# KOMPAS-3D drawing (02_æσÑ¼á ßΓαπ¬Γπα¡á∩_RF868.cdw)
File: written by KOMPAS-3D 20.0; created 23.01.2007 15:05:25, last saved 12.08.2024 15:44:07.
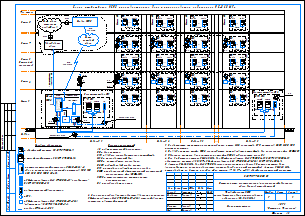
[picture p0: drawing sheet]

Sheet 1: A3, landscape

Document properties: Разработал: Антошин; Проверил: Тарасов; Утвердил: Шмончев; Н. контр.: Силаков; Количество листов документа: 1; Полное имя файла: \\s-tech\depts\Отдел_ПКО\Проекты\Типовые проекты МКД 2023\!Типовой проект\2_Типовой проект МКД_Радиоканал\02_Схема структурная_RF868.cdw; Материал: Многоквартирный жилой дом с использованием УСПД

Title block, sheet 1: Наименование: ВЛСТ 858.00.001 С3; designation: ВЛСТ 1177.02.000 С3; Количество листов документа: 8; organisation: АО ГК / "Системы и Технологии"; Форматы листов документа: A3; stored path: Y:\Проекты\ЭнергоКурган\Типовой проект\02_Рабочая док. общ\Е1_001_Сх деления.cdw; cell 302: Система учета электроэнергии (с организацией удаленного / сбора данных) потребителей; cell 303: Типовой проект ИСУЭ / многоквартирного дома с использованием / радиоканала (F2/868 МГц); cell 304: Схема структурная АИИС; cell 320: Р

Referenced files in \\Helios\отдел_пко\Общая папка Компас\_Addons\Signatures\: Signatures.lfr|Тарасов, Signatures.lfr, Signatures.lfr|Силаков, Signatures.lfr|Шмончев
Referenced files in C:\Program Files\ASCON\KOMPAS-3D V13\Libs\_Addons\Signatures\: Signatures.lfr
Referenced files: qlkzkl.frw, eiczbt.frw, hsklda.frw
Referenced files in C:\Program Files\ASCON\KOMPAS-3D v20\Sys\: Lighting.lts
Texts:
  Тарасов
  Силаков
  Шмончев
  Лит-Масса-Масштаб
  Материал-Предприятие
  Normal
  TXT
  Plain Text
  Centerline
  Outline
  Этаж 1
  ВВГнг(А)-LS 3х2.5
  Схема структурная ИСУЭ многоквартирного дома с использованием радиоканала RF-868 МГц
  Тех. этаж
  Шкаф
  УСПД
  ПЭФ
  RS-485
  SM160-02
  USB
  Link ST200
  Антенна GSM
  Электрощитовая №1
  ВРУ №1
  Сч. ОДПУ
  Сч. МОП
  ПРК
  ВРУ №2
  Электрощитовая №2
  RF-868
  Сч. Кв.1
  Сч. Кв.6
  ВОЛС
  Оборудование
  связи
  Этаж N
  GSM
  Осн. канал
  Сервер ИСУЭ
  Стояк ЭЭ
  Этаж 7
  Этаж 2
  Этаж 3
  (Этажи 4-6
  аналогично)
  Альтернативный канал
  (при необходимости)
  1. В зависимости от системы электроснабжения и типа МКД количество ВРУ, счетчиков ОДПУ, МОП, ИПУ
  может изменяться.
  2. На вводе питания шкафа УСПД рекомендуется устанавливать устройство для переключения фаз ПЭФ-301.
  3. Удаленные счетчики (вне помещения со шкафом УСПД), подключаются через ПЛ.
  4. Поз. 1 - Внешняя антенна RF-868 МГц для RF-формирователя Link ST200.F2-K1 ВЛСТ 339.10.000-К1,
  абонентских счетчиков КВАНТ и RF-формирователя Link ST200.F2-09-SMA ВЛСТ 339.04.000-9s.
  5. Антенна RF-868 МГц для Link ST200 должна располагаться не ближе 1.5 метра от стены дома
  (рекомендуется на плоскую поверхность крыши подъезда или иной пристройки). Антенны RF-868 МГц
  устанавливать на 2 этаже и каждые +5 по этажам (7, 12, 17 и т.д.) в одной горизонтальной плоскости.
  Подъезд 1
  Подъезд 2
  Подъезд K
  Подъезд 3
  Подвал
  Перечень сокращений
  АВ - автоматический выключатель;
  БП - блок питания;
  ВРУ - вводное распределительное устройство;
  МКД - многоквартирный дом;
  МОП -  места общего пользования;
  ОДПУ - общедомовой прибор учета;
  ПРК - пассивная разветвительная коробка;
  ПЭФ - универсальный автоматический электронный
  ИСУЭ - интеллектуальня система учета
  электроэнергии;
  ПЛ - преобразователь линии.
  - однофазный счетчик КВАНТ ST1000-9;
  - трехфазный счетчик КВАНТ ST2000-12;
  - интеллектуальный контроллер SM160-02М/xД,
  где х - максимальное количество счетчиков (100, 150,
  - автоматический выключатель;
  - RF-формирователь Link ST200.F2-K1 "координатор"
  (ВЛСТ 339.10.000-К1);
  - ПРК;
  - кабель FTP4-4х2х0,51.
  - RF-формирователь Link ST200.F2-09-SMA
  "повторитель" (ВЛСТ 339.04.000-9s);
  6. Для опроса приборов учета абонентов возможно применение
  RF-формирователя Link ST200.F2-09-SMA, который является
  репитером с внешней антенной.
  Сети
  сотовой
  Сети связи
  интернет
  провайдеров
  Штрих осн. черн
  POLYLINE_STYLE_0.25_RGB_0_0_0
  Питание
  Стили документа
  Разраб.
  Н.контр
  Утв.
  Многоквартирный жилой дом
  с использованием УСПД
  Структурная схема
  Антошин
  Схема структурная
  03 Рабочие чертежи основного комплекта. ГОСТ Р 21.1101-2009 Ф3
Dimensions and other numbers on the sheet: 2c5; 1c5; 3с5; 220В; 24В; 1; 340.00.png; 7; 04.23; 8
